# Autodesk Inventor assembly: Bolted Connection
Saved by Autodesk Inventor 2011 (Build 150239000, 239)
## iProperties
Created: 2020-12
Part Number: Bolted Connection
Document SubType Name: Assembly
Designer: PC
ClientObjectVersion: 1
Author: PC
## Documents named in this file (3)
- C:\Users\PC\Documents\Inventor\workshop-crane-powered-by-drill\pivot-arm\Design Accelerator\Bolted Connection1.iam
- C:\Users\PC\Documents\Inventor\Content Center Files\R2011\en-US\DIN 931-1\DIN 931-1 - M14 x 90.ipt
- C:\Users\PC\Documents\Inventor\Content Center Files\R2011\en-US\DIN 555\DIN 555-5 - M14.ipt
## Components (2 placed, 2 different names)
1. DIN 931-1 - replaced by DIN EN 24014 M14 x 90:1
2. DIN 555 - replaced by DIN EN 24034 M14:1
